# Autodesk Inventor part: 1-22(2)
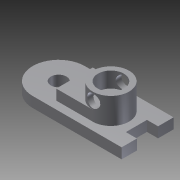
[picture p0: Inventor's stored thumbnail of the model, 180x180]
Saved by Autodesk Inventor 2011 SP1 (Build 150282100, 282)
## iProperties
Created: 2014-02
Part Number: 1-22(2)
Document SubType Name: Modeling
Designer: Administrator
Density: 1 g/cm^3
Author: Administrator
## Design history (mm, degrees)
sketch "草图1"
  geometry: L1 (-12.11, 10)-(22.11, 10); L2 (22.11, 10)-(22.11, -10); L3 (22.11, -10)-(-12.11, -10); A1 r 10 centre (-12.11, 0) between (-12.11, 10) and (-12.11, -10); 3 further points
  constraints: 6 end point, 2 point on circle, 1 centre point, 1 horizontal, 1 horizontal alignment, 1 midpoint, 1 parallel, 1 perpendicular, 1 vertical alignment
extrude "拉伸1" new body sketch "草图1" distance "d1" = 4; taper "d2" = 0 deg
sketch "草图2"
  geometry: L1 (22.11, 10)-(22.11, -10) reference; L2 (-12.11, 10)-(22.11, 10) reference; L3 (22.11, -4.113)-(17.836, -4.113); L4 (17.836, -4.113)-(17.836, 4.023); L5 (17.836, 4.023)-(22.11, 4.023); C1 r 3 at (-12.11, 0); A1 r 10 centre (-12.11, 0) between (-12.11, 10) and (-12.11, -10) reference; 1 further point
  constraints: 6 end point, 2 perpendicular, 2 point on line, 1 centre point, 1 coincident, 1 parallel
  dimensions: "d3" = 6 diameter of C1
extrude "拉伸2" cut sketch "草图2" stored distance "d4" = 4; taper "d5" = 0 deg
sketch "草图3"
  geometry: C1 r 7 at (7.983, 0); 1 further point
  constraints: 1 centre point
  dimensions: "d6" = 14 diameter of C1
extrude "拉伸3" join sketch "草图3" distance "d7" = 10; taper "d8" = 0 deg
sketch "草图4"
  geometry: C1 r 7 at (0, 0) reference; C2 r 5 at (0, 0); 1 further point
  constraints: 1 centre point, 1 coincident
  dimensions: "d9" = 10 diameter of C2
extrude "拉伸4" cut sketch "草图4" distance "d10" = 6; taper "d11" = 0 deg
sketch "草图5"
  geometry: L1 (8.019, -7)-(-6.074, -7); L2 (-6.074, -7)-(-6.074, 7.068); L3 (-6.074, 7.068)-(8.019, 7.068); L4 (8.019, 7.068)-(8.019, 7); A1 r 7 centre (7.983, 0) between (8.019, -7) and (8.019, 7) reference; 1 further point
  constraints: 8 end point, 2 parallel, 2 point on circle, 1 horizontal, 1 perpendicular
extrude "拉伸5" join sketch "草图5" distance "d12" = 4; taper "d13" = 0 deg
sketch "草图6"
  geometry: L1 (25.093, 8)-(15.093, 8) reference; C1 r 2.5 at (20.093, 10.935); 1 further point
  constraints: 1 centre point
  dimensions: "d14" = 5 diameter of C1
extrude "拉伸6" cut sketch "草图6" stored distance "d15" = 4; taper "d16" = 0 deg
sketch "草图7"
  geometry: C1 r 1.25 at (0, 2.5); C2 r 1.25 at (0, -2.5); 1 further point
  constraints: 2 centre point
extrude "拉伸7" cut sketch "草图7" stored distance "d19" = 4; taper "d20" = 0 deg
node "实体1"
